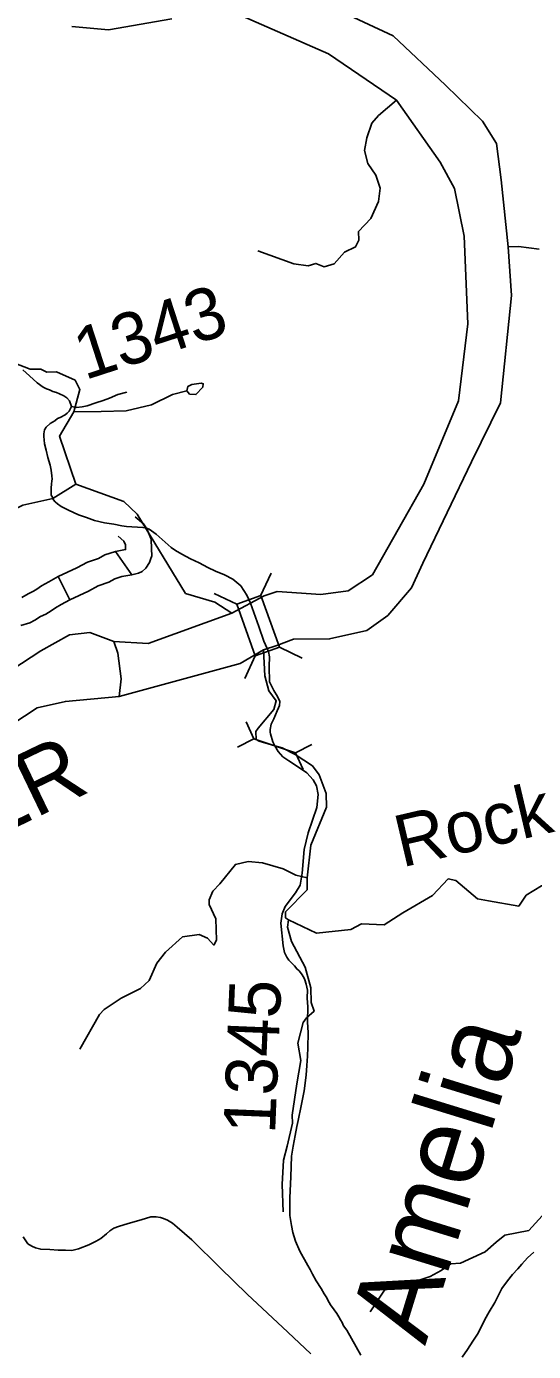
# Model space of a CAD drawing. Extents: x 1347947 to 1350662, y 1027710 to 1030532.
# Drawn here: x 1348203.5 to 1348247.6, y 1028931.2 to 1029046.3 of the extents above; entities that cross this region are included whole.
import ezdxf

# ---------------------------------------------------------------- set-up
doc = ezdxf.new("R2010")
doc.units = 0
doc.layers.add('Default', color=7, linetype='Continuous')
doc.layers.add('Prop Leader Line Light', color=7, linetype='Continuous')

msp = doc.modelspace()

# ---------------------------------------------------------------- linework, layer by layer
at = {"layer": 'Default'}
for p, q in [((1348211.29, 1029000.72), (1348212.7, 1028998.71)), ((1348206.3, 1028998.54), (1348207.31, 1028996.53)), ((1348223.87, 1028996.88), (1348224.8, 1028998.85)), ((1348221.82, 1028996.14), (1348219.85, 1028997.07)), ((1348227.49, 1028991.47), (1348225.52, 1028992.4)), ((1348222.5, 1028989.68), (1348223.42, 1028991.65)), ((1348222.63, 1028985.92), (1348223.3, 1028984.46)), ((1348221.88, 1028983.71), (1348223.3, 1028984.46)), ((1348226.91, 1028983.23), (1348223.3, 1028984.46)), ((1348228.33, 1028983.97), (1348226.91, 1028983.23)), ((1348227.58, 1028981.77), (1348226.91, 1028983.23))]:
    msp.add_line(p, q, dxfattribs=at)
for points in [[(1348221.39, 1028995.36), (1348224.2, 1028996.87), (1348225.31, 1028997.24), (1348229.12, 1028997), (1348231.48, 1028997.3), (1348233.6, 1028998.69), (1348238.07, 1029006.58), (1348241.08, 1029013.82), (1348241.89, 1029020.51), (1348241.57, 1029028.12), (1348240.72, 1029032.27), (1348239.5, 1029034.57), (1348235.69, 1029039.95), (1348229.78, 1029043.96), (1348220.92, 1029047.85)], [(1348226.75, 1028993.12), (1348229.88, 1028993.13), (1348233.1, 1028993.87), (1348234.95, 1028995.17), (1348237, 1028997.58), (1348237.98, 1028999.72), (1348242.22, 1029008.52), (1348244.72, 1029013.65), (1348245.67, 1029022.98), (1348245.4, 1029027.21), (1348244.78, 1029033.02), (1348244.38, 1029036.19), (1348243.16, 1029038.13), (1348239.95, 1029041.26), (1348235.39, 1029045.54), (1348230.73, 1029047.7)], [(1348216.16, 1029047.02), (1348210.67, 1029046.07), (1348207.47, 1029046.36)], [(1348223.64, 1029026.85), (1348226.77, 1029025.72), (1348228.03, 1029025.54), (1348228.68, 1029025.76), (1348229.4, 1029025.47), (1348230.29, 1029025.71), (1348231.16, 1029026.73), (1348232.14, 1029027.2), (1348232.41, 1029027.78), (1348232.4, 1029028.54), (1348233.47, 1029029.65), (1348234.14, 1029031.15), (1348234.27, 1029032.29), (1348233.9, 1029033.44), (1348233.19, 1029034.44), (1348232.91, 1029035.56), (1348233.11, 1029036.67), (1348233.56, 1029037.94), (1348234.13, 1029038.6), (1348235.69, 1029039.95)], [(1348204.8, 1029016.57), (1348203.86, 1029016.56), (1348201.53, 1029017.46), (1348200.55, 1029018.32), (1348198.13, 1029021.54), (1348194.97, 1029022.73), (1348192.59, 1029024.93), (1348189.06, 1029027.18), (1348183.06, 1029028.77), (1348181.45, 1029028.74), (1348177.5, 1029029.87), (1348175.38, 1029031.29), (1348171.91, 1029032.08)], [(1348245.4, 1029027.21), (1348246.28, 1029027.23), (1348248.08, 1029027.01)], [(1348203.21, 1029016.5), (1348203.79, 1029015.99), (1348204.46, 1029015.38), (1348205, 1029015.01), (1348205.29, 1029014.87), (1348205.54, 1029014.78), (1348205.84, 1029014.64), (1348206.15, 1029014.53), (1348206.4, 1029014.42), (1348206.78, 1029014.24), (1348207.06, 1029014.08), (1348207.27, 1029013.83), (1348207.45, 1029013.33)], [(1348221.39, 1028995.36), (1348219.92, 1028996.32), (1348217.37, 1028997.09), (1348213.15, 1029003.96), (1348211.99, 1029005.06), (1348207.84, 1029006.59), (1348206.41, 1029010.74), (1348207.65, 1029012.86), (1348208.19, 1029014.79), (1348207.77, 1029015.62), (1348206.15, 1029016.35), (1348205.31, 1029016.31), (1348204.8, 1029016.57)], [(1348217.46, 1029014.68), (1348217.72, 1029014.39), (1348218.26, 1029014.36), (1348218.86, 1029015.01), (1348218.9, 1029015.3), (1348218.72, 1029015.36), (1348217.92, 1029015.23), (1348217.55, 1029015.06), (1348217.46, 1029014.68)], [(1348207.45, 1029013.33), (1348207.88, 1029013.24), (1348208.38, 1029013.31), (1348208.82, 1029013.37), (1348209.58, 1029013.64), (1348210.19, 1029013.84), (1348210.74, 1029014.06), (1348211.49, 1029014.36), (1348212.26, 1029014.57)], [(1348207.65, 1029012.86), (1348210.04, 1029012.89), (1348212.2, 1029012.95), (1348214.39, 1029013.47), (1348216.23, 1029014.36), (1348217.46, 1029014.68)], [(1348207.84, 1029006.59), (1348205.83, 1029005.34), (1348203.22, 1029004.76), (1348202.64, 1029004.45), (1348202.08, 1029004.3), (1348201.14, 1029004.36), (1348199.91, 1029004.8), (1348198.52, 1029005.08), (1348197.49, 1029005.64), (1348196.53, 1029006.1), (1348194.47, 1029006.44), (1348192.53, 1029007.38), (1348190.52, 1029008.63), (1348187.82, 1029011.23), (1348187.13, 1029011.86), (1348186.11, 1029013.79)], [(1348207.45, 1029013.33), (1348207.35, 1029013.09), (1348207.24, 1029012.92), (1348207.09, 1029012.76), (1348206.89, 1029012.61), (1348206.47, 1029012.37), (1348206.24, 1029012.27), (1348206, 1029012.07), (1348205.6, 1029011.84), (1348205.25, 1029011.54), (1348205.12, 1029011.29), (1348205.05, 1029010.96), (1348205.04, 1029010.71), (1348205.07, 1029010.44), (1348205.12, 1029010.09), (1348205.25, 1029009.53), (1348205.39, 1029008.89), (1348205.59, 1029008.24), (1348205.68, 1029007.78), (1348205.73, 1029007.29), (1348205.76, 1029007.02), (1348205.73, 1029006.88), (1348205.72, 1029006.58), (1348205.68, 1029006.27), (1348205.68, 1029005.92), (1348205.68, 1029005.63), (1348205.79, 1029005.44), (1348205.87, 1029005.24), (1348206.04, 1029005.04), (1348206.23, 1029004.88), (1348206.56, 1029004.63), (1348207.2, 1029004.33), (1348208.05, 1029003.92), (1348208.75, 1029003.68), (1348209.45, 1029003.43), (1348210.33, 1029003.22), (1348211.13, 1029003.1), (1348211.84, 1029002.95), (1348212.24, 1029002.9)], [(1348212.98, 1029003.75), (1348213.7, 1029003.12), (1348213.99, 1029002.7), (1348214.37, 1029001.81), (1348214.4, 1029000.95), (1348214.42, 1029000.35), (1348214.31, 1029000.02), (1348214.22, 1028999.76), (1348213.92, 1028999.28), (1348213.59, 1028999), (1348213.26, 1028998.84), (1348212.7, 1028998.71), (1348211.84, 1028998.54), (1348211.22, 1028998.35), (1348210.7, 1028998.07), (1348209.76, 1028997.74), (1348208.93, 1028997.29), (1348207.31, 1028996.53), (1348206.56, 1028996.12), (1348206.06, 1028995.84), (1348205.68, 1028995.57), (1348205.23, 1028995.29), (1348204.77, 1028995.07), (1348204.26, 1028994.75), (1348203.82, 1028994.53), (1348203.06, 1028994.29)], [(1348223.72, 1028994.2), (1348223, 1028996.23), (1348222.7, 1028996.92), (1348222.16, 1028997.74), (1348221.48, 1028998.32), (1348220.75, 1028998.71), (1348219.97, 1028999.01), (1348219.29, 1028999.35), (1348218.55, 1028999.73), (1348217.8, 1029000.09), (1348217.04, 1029000.5), (1348216.5, 1029000.81), (1348216.12, 1029001.08), (1348214.81, 1029002.23), (1348214.19, 1029002.67), (1348213.97, 1029002.75), (1348213.66, 1029002.8), (1348212.24, 1029002.9)], [(1348211.51, 1029002.05), (1348212.01, 1029001.61), (1348212.01, 1029001.61), (1348212.14, 1029001.31), (1348212.15, 1029000.9), (1348211.29, 1029000.72), (1348210.35, 1029000.44), (1348209.79, 1029000.13), (1348208.85, 1028999.8), (1348207.92, 1028999.3), (1348206.3, 1028998.54), (1348205.48, 1028998.09), (1348204.86, 1028997.75), (1348204.43, 1028997.45), (1348204.14, 1028997.27), (1348203.69, 1028997.05), (1348203.15, 1028996.72)], [(1348221.39, 1028995.36), (1348214.11, 1028992.74), (1348211.12, 1028992.92), (1348209.06, 1028993.68), (1348207.27, 1028993.48), (1348204.79, 1028992.09), (1348198.97, 1028988.31)], [(1348232.58, 1028930.89), (1348231.37, 1028933.07), (1348231.09, 1028933.45), (1348230.96, 1028933.72), (1348230.83, 1028933.96), (1348230.67, 1028934.22), (1348230.52, 1028934.5), (1348230.29, 1028934.82), (1348229.97, 1028935.26), (1348229.84, 1028935.48), (1348229.57, 1028935.95), (1348229.42, 1028936.23), (1348229.14, 1028936.67), (1348228.72, 1028937.36), (1348228.39, 1028937.92), (1348228.2, 1028938.33), (1348228, 1028938.69), (1348227.29, 1028939.94), (1348226.92, 1028940.8), (1348226.67, 1028941.56), (1348226.57, 1028942.16), (1348226.43, 1028943.02), (1348226.41, 1028944.56), (1348226.5, 1028946.38), (1348226.57, 1028948.17), (1348226.7, 1028949.05), (1348226.89, 1028949.99), (1348227.02, 1028950.76), (1348227.14, 1028951.28), (1348227.4, 1028952.55), (1348227.67, 1028953.86), (1348227.83, 1028955.23), (1348227.91, 1028956.06), (1348227.96, 1028956.86), (1348228, 1028957.64), (1348228.03, 1028958.9), (1348227.97, 1028959.87), (1348227.98, 1028961.19), (1348227.95, 1028961.5), (1348227.93, 1028961.94), (1348227.96, 1028962.62), (1348227.83, 1028963.14), (1348227.74, 1028963.51), (1348227.65, 1028963.72), (1348227.43, 1028964.03), (1348227.22, 1028964.28), (1348227.02, 1028964.45), (1348226.82, 1028964.72), (1348226.54, 1028965), (1348226.35, 1028965.21), (1348226.16, 1028965.48), (1348225.95, 1028965.87), (1348225.85, 1028966.47), (1348225.65, 1028968.42), (1348225.75, 1028969.24), (1348226.02, 1028969.88), (1348226.91, 1028971.07), (1348227.31, 1028971.74), (1348227.49, 1028972.77), (1348227.68, 1028974.84), (1348228.03, 1028976.28), (1348228.77, 1028978.49), (1348228.89, 1028979.6), (1348228.74, 1028980.37), (1348228.44, 1028980.89), (1348227.9, 1028981.49), (1348226.56, 1028982.39), (1348226.33, 1028982.53), (1348225.82, 1028982.87), (1348225.41, 1028983.35), (1348225.12, 1028983.84), (1348224.94, 1028984.19), (1348224.74, 1028984.87), (1348224.71, 1028985.04), (1348224.72, 1028985.26), (1348224.81, 1028985.71), (1348225.02, 1028986.18), (1348225.33, 1028986.89), (1348225.45, 1028987.13), (1348225.53, 1028987.35), (1348225.56, 1028987.7), (1348225.35, 1028988.13), (1348225.02, 1028988.65), (1348224.67, 1028989.39), (1348224.64, 1028990.72), (1348224.65, 1028991.57), (1348224.56, 1028992.04), (1348224.17, 1028992.93), (1348223.72, 1028994.2)], [(1348224.13, 1028992.17), (1348222.1, 1028990.98), (1348211.59, 1028988.12), (1348206.93, 1028987.7), (1348204.48, 1028987.13), (1348196.74, 1028982.06), (1348193.07, 1028980.37), (1348191, 1028979.57), (1348182.98, 1028974.25), (1348181.62, 1028974.41), (1348178.33, 1028973.56), (1348173.63, 1028972.68), (1348165.25, 1028969.18), (1348161.18, 1028966.93), (1348159.42, 1028964.51), (1348155.92, 1028962.61), (1348155.72, 1028962.4)], [(1348211.59, 1028988.12), (1348211.76, 1028989.66), (1348211.47, 1028991.88), (1348211.12, 1028992.92)], [(1348227.93, 1028972.37), (1348228.24, 1028975.21), (1348229.61, 1028978.52), (1348229.58, 1028979.69), (1348228.98, 1028981.32), (1348228.38, 1028982.09), (1348226.88, 1028983.09), (1348225.77, 1028983.68), (1348225.12, 1028983.84), (1348223.77, 1028984.25), (1348223.51, 1028984.4), (1348223.46, 1028985.08), (1348223.68, 1028985.37), (1348225.04, 1028987.01), (1348225.24, 1028987.74), (1348224.6, 1028988.63), (1348224.25, 1028989.93), (1348224.13, 1028992.17)], [(1348224.13, 1028992.17), (1348225.3, 1028992.57), (1348226.75, 1028993.12)], [(1348208.18, 1028957.48), (1348209.89, 1028960.49), (1348210.3, 1028960.92), (1348211.77, 1028961.9), (1348213.45, 1028962.74), (1348214.21, 1028963.45), (1348214.87, 1028964.95), (1348215.62, 1028965.91), (1348217.1, 1028967.23), (1348218.54, 1028967.44), (1348219.27, 1028967.12), (1348219.81, 1028966.53), (1348220.06, 1028966.95), (1348220, 1028968.81), (1348219.41, 1028970.05), (1348219.41, 1028970.46), (1348219.72, 1028971.21), (1348220.35, 1028971.86), (1348221.69, 1028973.53), (1348222.81, 1028973.8), (1348224.05, 1028973.67), (1348225.84, 1028973.14), (1348226.94, 1028972.61), (1348227.93, 1028972.37)], [(1348249.6, 1028972.12), (1348248.29, 1028971.67), (1348246.97, 1028970.87), (1348246.32, 1028969.92), (1348243.68, 1028970.38), (1348242.73, 1028970.54), (1348240.86, 1028972.13), (1348240.17, 1028972.27), (1348238.83, 1028970.83), (1348236.24, 1028969.34), (1348234.62, 1028968.29), (1348232.66, 1028968.36), (1348231.71, 1028967.88), (1348228.75, 1028967.57), (1348226.31, 1028968.72), (1348226.06, 1028968.89), (1348226.05, 1028969.42), (1348227.94, 1028971.33), (1348227.93, 1028972.37)], [(1348226.31, 1028968.72), (1348226.23, 1028968.07), (1348226.57, 1028966.83), (1348227.77, 1028964.62), (1348228.26, 1028962.81), (1348228.28, 1028961.54), (1348228.53, 1028960.78), (1348227.87, 1028960.19), (1348227.57, 1028959.79), (1348227.11, 1028958.01), (1348227.39, 1028956.49), (1348227.03, 1028954.47), (1348226.63, 1028951.76), (1348226.65, 1028951.04), (1348226.18, 1028949.06), (1348225.86, 1028947.85), (1348225.76, 1028945.72), (1348225.85, 1028943.34)], [(1348203.25, 1028941.18), (1348203.66, 1028940.58), (1348204, 1028940.36), (1348204.32, 1028940.21), (1348204.78, 1028940.1), (1348205.57, 1028940.06), (1348206.3, 1028940.02), (1348206.92, 1028940.01), (1348207.48, 1028939.99), (1348208.06, 1028940.12), (1348208.96, 1028940.48), (1348209.6, 1028940.79), (1348210, 1028941.03), (1348210.49, 1028941.43), (1348210.79, 1028941.7), (1348211.13, 1028941.92), (1348211.55, 1028942.08), (1348212.39, 1028942.32), (1348213.3, 1028942.6), (1348213.89, 1028942.78), (1348214.35, 1028942.91), (1348214.82, 1028942.92), (1348215.18, 1028942.86), (1348215.44, 1028942.77), (1348215.78, 1028942.63), (1348216.24, 1028942.37), (1348216.64, 1028942), (1348217.92, 1028940.92), (1348220.36, 1028938.49), (1348222.71, 1028936.19), (1348226.24, 1028932.88), (1348228.24, 1028931.02)], [(1348248.35, 1028943), (1348247.19, 1028941.73), (1348245.1, 1028941.31), (1348244.34, 1028940.72), (1348243.41, 1028939.87), (1348241.24, 1028938.89), (1348240.4, 1028938.84), (1348239.58, 1028938.25), (1348238.63, 1028937.73), (1348236.78, 1028937.11), (1348235.23, 1028936.88), (1348234.66, 1028936.53), (1348233.39, 1028934.65)], [(1348247.62, 1028939.83), (1348247.06, 1028939.35), (1348246.57, 1028938.81), (1348246.22, 1028938.4), (1348245.77, 1028937.9), (1348245.33, 1028937.35), (1348244.85, 1028936.68), (1348244.24, 1028935.46), (1348243.75, 1028934.67), (1348243.37, 1028933.99), (1348242.79, 1028932.81), (1348242.32, 1028932.11), (1348241.85, 1028931.38), (1348241.39, 1028930.73)]]:
    msp.add_lwpolyline(points, dxfattribs=at)
msp.add_lwpolyline([(1348223.42, 1028991.65), (1348221.81, 1028996.14), (1348223.91, 1028996.89), (1348225.52, 1028992.4)], close=True, dxfattribs=at)

# ---------------------------------------------------------------- texts
for s, height, rotation, p in [('RIVER', 5.625, 25.7241, (1348188.49, 1028969.92)), ('Rock', 4.5, 13.2182, (1348236.16, 1028973.26))]:
    msp.add_text(s, height=height, rotation=rotation, dxfattribs=at).set_placement(p)
at = {"layer": 'Prop Leader Line Light'}
for s, height, rotation, p in [('1343', 4.5, 17.994, (1348208.6, 1029015.6)), ('1345', 4.5, 87.6418, (1348225.14, 1028950.06)), ('Amelia', 7, 72.8834, (1348238.18, 1028931.66))]:
    msp.add_text(s, height=height, rotation=rotation, dxfattribs=at).set_placement(p)

doc.saveas('drawing.dxf')
